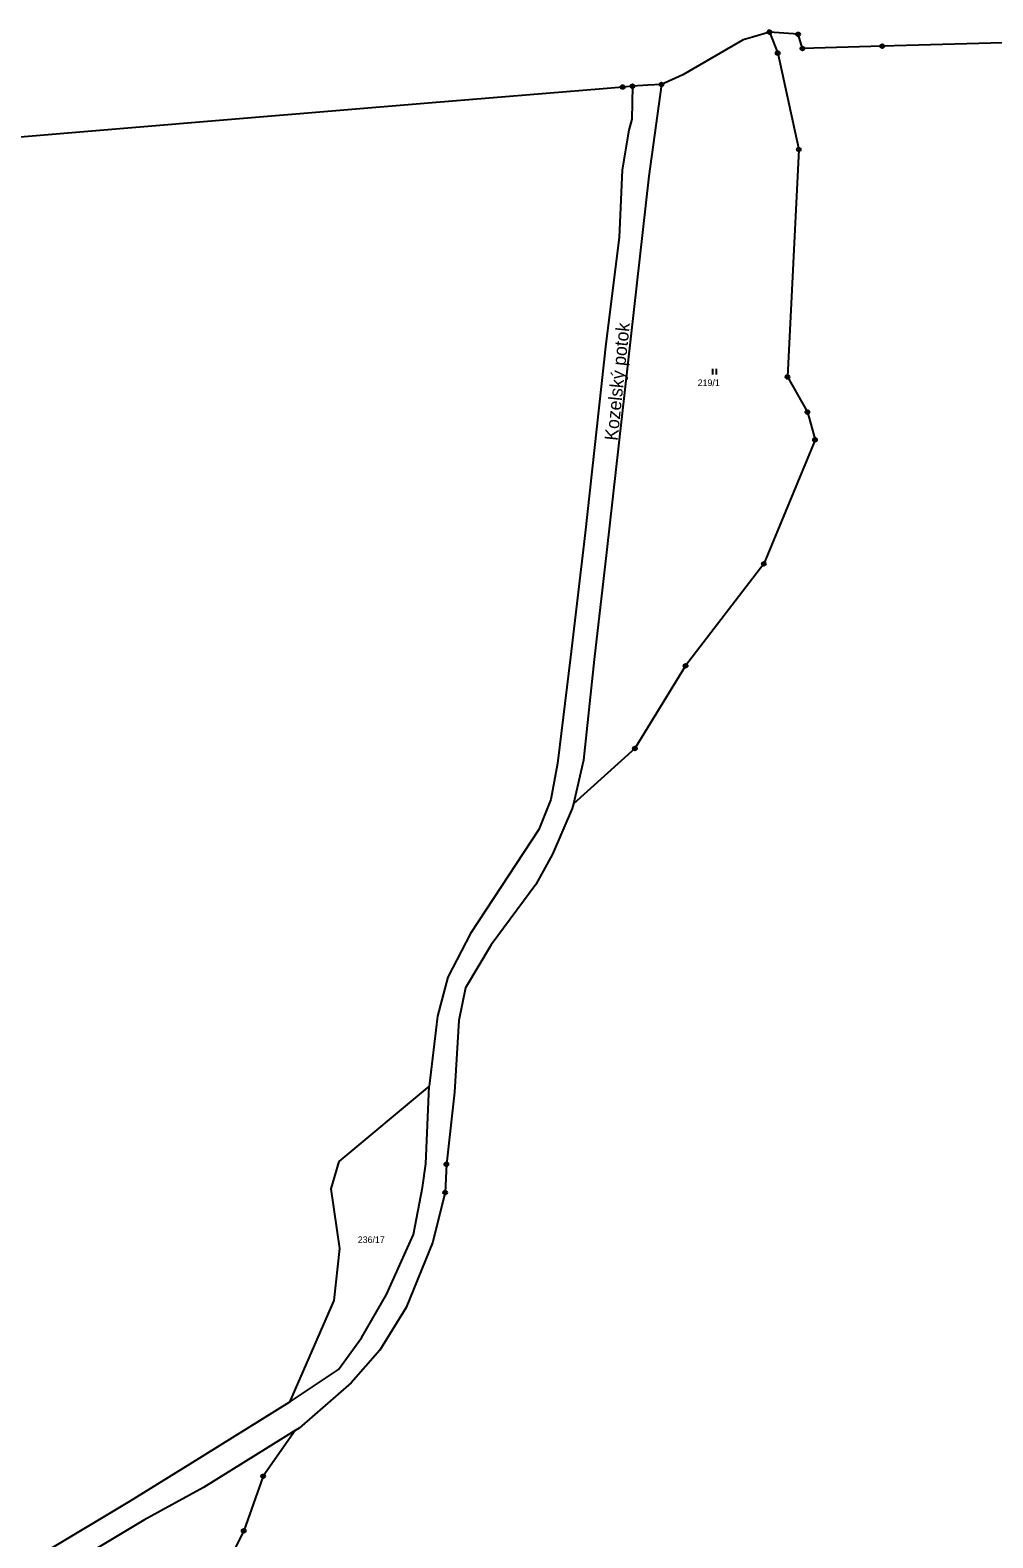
# Model space of a CAD drawing. Extents: x -885985 to -883535, y -1030025 to -1027941.
# Drawn here: x -884271.3 to -884022.6, y -1028330.5 to -1027940.9 of the extents above; entities that cross this region are included whole.
import ezdxf
from ezdxf.enums import TextEntityAlignment as Align

# ---------------------------------------------------------------- set-up
doc = ezdxf.new("R2010")
doc.units = 0
doc.header["$LTSCALE"] = 0.68
for name, color, linetype, lineweight in [('1', 7, 'Continuous', 25), ('3', 7, 'Continuous', 25), ('7', 7, 'Continuous', 13), ('8', 7, 'Continuous', 25)]:
    doc.layers.add(name, color=color, linetype=linetype, lineweight=lineweight)
doc.layers.add('2', color=7, linetype='Continuous')

msp = doc.modelspace()

# ---------------------------------------------------------------- linework, layer by layer
at = {"layer": '1'}
for p, q in [((-884084.77, -1027942.73), (-884087.16, -1027943.43)), ((-884080.37, -1027941.44), (-884084.77, -1027942.73)), ((-884072.93, -1027942.01), (-884080.37, -1027941.44)), ((-884080.37, -1027941.44), (-884078.22, -1027946.87)), ((-884071.83, -1027945.69), (-884072.93, -1027942.01)), ((-884051.21, -1027945.09), (-884071.83, -1027945.69)), ((-883991.33, -1027943.36), (-884051.21, -1027945.09)), ((-884078.22, -1027946.87), (-884072.76, -1027971.78)), ((-884123.3, -1027956.06), (-884167.47, -1027959.73)), ((-884118.26, -1027955.64), (-884123.3, -1027956.06)), ((-884115.72, -1027955.43), (-884118.26, -1027955.64)), ((-884115.72, -1027955.43), (-884115.88, -1027963.94)), ((-884111.77, -1027955.19), (-884115.72, -1027955.43)), ((-884108.26, -1027954.97), (-884111.77, -1027955.19)), ((-884108.26, -1027954.97), (-884111.48, -1027978.65)), ((-884167.47, -1027959.73), (-884217.25, -1027963.87)), ((-884217.25, -1027963.87), (-884319.1, -1027972.34)), ((-884115.88, -1027963.94), (-884116.68, -1027966.77)), ((-884116.68, -1027966.77), (-884118.4, -1027977.07)), ((-884072.76, -1027971.78), (-884075.68, -1028030.55)), ((-884111.48, -1027978.65), (-884122.44, -1028075.91)), ((-884118.4, -1027977.07), (-884119.19, -1027994.54)), ((-884119.19, -1027994.54), (-884122.61, -1028022.03)), ((-884122.61, -1028022.03), (-884127.93, -1028070.85)), ((-884075.68, -1028030.55), (-884070.55, -1028039.63)), ((-884070.55, -1028039.63), (-884068.58, -1028046.77)), ((-884068.58, -1028046.77), (-884081.81, -1028078.84)), ((-884127.93, -1028070.85), (-884131.72, -1028102.91)), ((-884122.44, -1028075.91), (-884125.65, -1028103.56)), ((-884081.81, -1028078.84), (-884102.02, -1028105.18)), ((-884131.72, -1028102.91), (-884135.08, -1028130.39)), ((-884125.65, -1028103.56), (-884128.37, -1028129.59)), ((-884102.02, -1028105.18), (-884115.11, -1028126.56)), ((-884115.11, -1028126.56), (-884131, -1028140.82)), ((-884135.08, -1028130.39), (-884136.79, -1028139.77)), ((-884128.37, -1028129.59), (-884131, -1028140.82)), ((-884136.79, -1028139.77), (-884139.96, -1028147.49)), ((-884131.29, -1028142.08), (-884136.37, -1028153.86)), ((-884131, -1028140.82), (-884131.29, -1028142.08)), ((-884139.96, -1028147.49), (-884157.6, -1028174.33)), ((-884136.37, -1028153.86), (-884140.69, -1028161.73)), ((-884140.69, -1028161.73), (-884152.21, -1028177.27)), ((-884157.6, -1028174.33), (-884163.46, -1028185.62)), ((-884152.21, -1028177.27), (-884158.89, -1028188.39)), ((-884163.46, -1028185.62), (-884166.14, -1028195.73)), ((-884158.89, -1028188.39), (-884160.63, -1028196.82)), ((-884166.14, -1028195.73), (-884168.28, -1028213.76)), ((-884160.63, -1028196.82), (-884161.67, -1028215.35)), ((-884168.28, -1028213.76), (-884191.59, -1028233.3)), ((-884169.12, -1028233.87), (-884168.28, -1028213.76)), ((-884161.67, -1028215.35), (-884163.81, -1028233.98)), ((-884191.59, -1028233.3), (-884193.64, -1028240.29)), ((-884169.94, -1028239.97), (-884169.12, -1028233.87)), ((-884163.81, -1028233.98), (-884164.13, -1028241.3)), ((-884193.64, -1028240.29), (-884191.41, -1028255.76)), ((-884172.28, -1028252.15), (-884169.94, -1028239.97)), ((-884164.13, -1028241.3), (-884167.4, -1028254.3)), ((-884179.25, -1028267.65), (-884172.28, -1028252.15)), ((-884191.41, -1028255.76), (-884192.92, -1028269.16)), ((-884167.4, -1028254.3), (-884174.18, -1028271.02)), ((-884185.71, -1028278.8), (-884179.25, -1028267.65)), ((-884192.92, -1028269.16), (-884204.32, -1028295.45)), ((-884174.18, -1028271.02), (-884180.98, -1028282.03)), ((-884191.72, -1028286.97), (-884185.71, -1028278.8)), ((-884180.98, -1028282.03), (-884188.37, -1028290.46)), ((-884204.32, -1028295.45), (-884191.72, -1028286.97)), ((-884188.37, -1028290.46), (-884201.85, -1028302.18)), ((-884204.32, -1028295.45), (-884230.07, -1028311.43)), ((-884202.83, -1028302.79), (-884226.59, -1028317.48)), ((-884202.83, -1028302.79), (-884211.15, -1028314.6)), ((-884201.85, -1028302.18), (-884202.83, -1028302.79)), ((-884230.07, -1028311.43), (-884245.65, -1028321.14)), ((-884211.15, -1028314.6), (-884216.17, -1028328.68)), ((-884226.59, -1028317.48), (-884241.93, -1028325.94)), ((-884245.65, -1028321.14), (-884267.33, -1028334.09)), ((-884241.93, -1028325.94), (-884264.57, -1028339.46)), ((-884216.17, -1028328.68), (-884225.88, -1028347.99))]:
    msp.add_line(p, q, dxfattribs=at)
msp.add_lwpolyline([(-884087.16, -1027943.43), (-884102.74, -1027952.51), (-884108.26, -1027954.97)], dxfattribs=at)
at = {"layer": '3'}
for p, q in [((-884095.001, -1028029.93), (-884095.001, -1028028.43)), ((-884094, -1028029.93), (-884094, -1028028.43))]:
    msp.add_line(p, q, dxfattribs=at)
at = {"layer": '8'}
for centre, radius in [((-884080.37, -1027941.4399), 0.5), ((-884080.37, -1027941.4399), 0.0303), ((-884072.93, -1027942.0099), 0.5), ((-884072.93, -1027942.0099), 0.0303), ((-884051.21, -1027945.0899), 0.5), ((-884051.21, -1027945.0899), 0.0303), ((-884078.22, -1027946.8699), 0.5), ((-884078.22, -1027946.8699), 0.0303), ((-884071.83, -1027945.6899), 0.5), ((-884071.83, -1027945.6899), 0.0303), ((-884118.26, -1027955.6399), 0.5), ((-884118.26, -1027955.6399), 0.0303), ((-884115.72, -1027955.4299), 0.5), ((-884115.72, -1027955.4299), 0.0303), ((-884108.26, -1027954.9699), 0.5), ((-884108.26, -1027954.9699), 0.0303), ((-884072.76, -1027971.7799), 0.5), ((-884072.76, -1027971.7799), 0.0303), ((-884075.68, -1028030.5499), 0.5), ((-884075.68, -1028030.5499), 0.0303), ((-884070.55, -1028039.6299), 0.5), ((-884070.55, -1028039.6299), 0.0303), ((-884068.58, -1028046.7699), 0.5), ((-884068.58, -1028046.7699), 0.0303), ((-884081.81, -1028078.8399), 0.5), ((-884081.81, -1028078.8399), 0.0303), ((-884102.02, -1028105.1799), 0.5), ((-884102.02, -1028105.1799), 0.0303), ((-884115.11, -1028126.5599), 0.5), ((-884115.11, -1028126.5599), 0.0303), ((-884163.81, -1028233.9799), 0.5), ((-884163.81, -1028233.9799), 0.0303), ((-884164.13, -1028241.2999), 0.5), ((-884164.13, -1028241.2999), 0.0303), ((-884211.15, -1028314.5999), 0.5), ((-884211.15, -1028314.5999), 0.0303), ((-884216.17, -1028328.6799), 0.5), ((-884216.17, -1028328.6799), 0.0303)]:
    msp.add_circle(centre, radius, dxfattribs=at)

# ---------------------------------------------------------------- texts
at = {"layer": '2'}
for s, p in [('219/1', (-884098.88, -1028032.905)), ('236/17', (-884186.69, -1028254.325))]:
    msp.add_text(s, height=1.7, dxfattribs=at).set_placement(p)
at = {"layer": '7'}
msp.add_text('Kozelský potok', height=3.4, rotation=84, dxfattribs=at).set_placement((-884117.9985, -1028031.9177), align=Align.CENTER)

doc.saveas('drawing.dxf')
